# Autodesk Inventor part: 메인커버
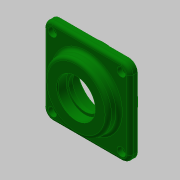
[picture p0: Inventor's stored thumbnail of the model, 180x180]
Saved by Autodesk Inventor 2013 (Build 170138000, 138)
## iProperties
Created: 2018-09
Part Number: 메인커버
Material: 일반
Document SubType Name: Modeling
Designer: mduedu
Density: 1 g/cm^3
Mass: 65.8536 g
Surface Area: 197.883 cm^2
Volume: 65.8536 cm^3
Author: mduedu
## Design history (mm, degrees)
sketch "스케치1"
  geometry: L1 (-40, -40)-(40, -40); L2 (40, -40)-(40, 40); L3 (40, 40)-(-40, 40); L4 (-40, 40)-(-40, -40); L5 (-40, -40)-(40, 40); L6 (40, -40)-(-40, 40); 1 further point
  constraints: 12 end point, 2 midpoint, 2 parallel, 1 horizontal, 1 perpendicular
  dimensions: "d0" = 80 distance of L3.end L2.end; "d1" = 80 distance of L2.end L1.end
extrude "돌출1" new body sketch "스케치1" distance "d2" = 7; taper "d3" = 0 deg
sketch "스케치2"
  geometry: C1 r 30 at (0, 0); 1 further point
  constraints: 1 centre point, 1 coincident
  dimensions: "d4" = 60 diameter of C1
extrude "돌출2" join sketch "스케치2" distance "d5" = 10; taper "d6" = 0 deg
sketch "스케치3"
  geometry: C1 r 32.5 at (0, 0); 1 further point
  constraints: 1 centre point, 1 coincident
  dimensions: "d7" = 65 diameter of C1
extrude "돌출3" join sketch "스케치3" distance "d8" = 9; taper "d9" = 0 deg
sketch "스케치4"
  geometry: L1 (-32.5, -9)-(32.5, -9) reference; L2 (30, 17)-(-30, 17) reference; L3 (0, 17)-(0, -9); L4 (0, -9)-(23.5, -9); L5 (23.5, -9)-(23.5, 5); L6 (23.5, 5)-(0, 5); L7 (0, 5)-(0, -9); L8 (0, 5)-(15, 5); L9 (15, 5)-(15, 8.7); L10 (15, 8.7)-(0, 8.7); L11 (0, 8.7)-(0, 5); L12 (0, 8.7)-(17.5, 8.7); L13 (17.5, 8.7)-(17.5, 17); L14 (17.5, 17)-(0, 17); L15 (0, 17)-(0, 8.7); 1 further point
  constraints: 26 end point, 6 parallel, 3 horizontal, 3 perpendicular, 2 midpoint, 1 point on line
  dimensions: "d10" = 14 distance of L4.end L5.end; "d12" = 8.3 distance of L12.end L13.end; "d13" = 35 diameter of L13 L3; "d14" = 30 diameter of L9 L3; "d15" = 47 diameter of L5 L3
revolve "회전1" sketch "스케치4" stored, may be unused: angle "d16" = 90 deg
fillet "모깎기1" dims "d17" = 8
fillet "모깎기2" dims "d18" = 3
fillet "모깎기3" dims "d19" = 3
chamfer "모따기1" distance "d20" = 0.8; stored, may be unused: second distance "d21" = 2, angle "d22" = 30 deg
chamfer "모따기2" distance "d23" = 1; stored, may be unused: second distance "d24" = 2, angle "d25" = 30 deg
fillet "모깎기4" dims "d26" = 0.3
sketch "스케치5"
  geometry: A1 r 8 centre (-32, 32) between (-32, 40) and (-40, 32) reference; A2 r 8 centre (-32, -32) between (-40, -32) and (-32, -40) reference; A3 r 8 centre (32, -32) between (32, -40) and (40, -32) reference; A4 r 8 centre (32, 32) between (40, 32) and (32, 40) reference; 5 further points
  constraints: 4 coincident
hole "구멍1" sketch "스케치5" at (-32, 32), (32, 32), (32, -32), (-32, -32) diameter "d27" = 4.5; stored, may be unused: countersink angle "d31" = 90 deg, drill point angle "d33" = 118 deg; dims "d28" = 6, "d29" = 8, "d30" = 4.4, "d32" = 8
node "솔리드1"
